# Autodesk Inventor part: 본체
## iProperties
Created: 2014-12
Part Number: 본체
Document SubType Name: Modeling
Designer: tw_037
Density: 2.71 g/cm^3
Material: 알루미늄-6061
Mass: 613.614 g
Surface Area: 665.795 cm^2
Volume: 226.426 cm^3
Author: tw_037
